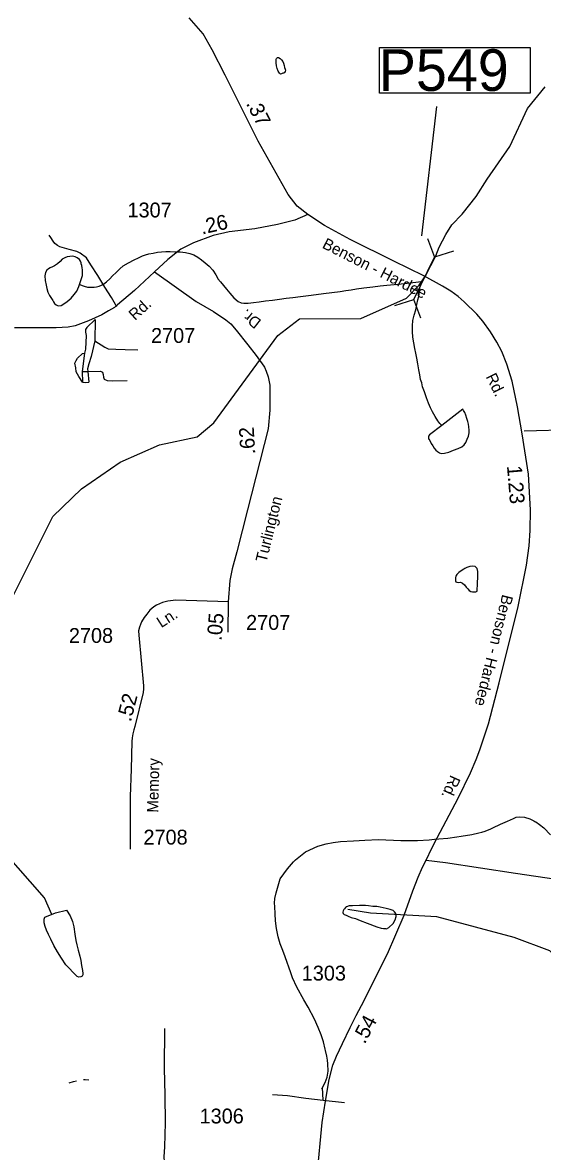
# Model space of a CAD drawing. Extents: x 2082433 to 2279600, y 546599 to 755198.
# Drawn here: x 2120566 to 2124939, y 611701 to 621201 of the extents above; entities that cross this region are included whole.
import ezdxf

# ---------------------------------------------------------------- set-up
doc = ezdxf.new("R2010")
doc.units = 0
for name, color, linetype in [('Exist Hydrographic Creek Single Shore', 7, 'Continuous'), ('Exist Hydrographic Misc Water Feature', 7, 'Continuous'), ('Exist Hydrographic Pond Under 1500 Sq Ft', 7, 'Continuous'), ('Exist Road Non-System Type 51', 7, 'Continuous'), ('Exist Road Secondary Mileage Hundredths English Label', 7, 'Continuous'), ('Exist Road Secondary Structure Pipe CELL', 7, 'Continuous'), ('Exist Road Secondary Structure Pipe Number Label', 7, 'Continuous'), ('Exist Road Secondary Type 51 Attributed', 7, 'Continuous'), ('Exist Road Secondary Type 51 Label', 7, 'Continuous'), ('Exist Road Secondary Type 51 Number Label', 7, 'Continuous')]:
    doc.layers.add(name, color=color, linetype=linetype)

msp = doc.modelspace()

# ---------------------------------------------------------------- linework, layer by layer
at = {"layer": 'Exist Hydrographic Creek Single Shore'}
for points in [[(2120366.5, 616142.3), (2120820.5, 617045), (2121061.5, 617276.4), (2121385.5, 617502.8), (2121717.6, 617646.9), (2122034.7, 617715.9), (2122175.5, 617831.2), (2122713.6, 618568.2), (2122896.5, 618708.9), (2123412.6, 618711.5), (2123795.7, 618881), (2123902.7, 618990.3), (2123955.2, 619069), (2124043.7, 619239), (2124069.9, 619311.8), (2124125.2, 619416.5), (2124177.5, 619497.9), (2124262.7, 619587.4), (2124380.8, 619738.6), (2124474.6, 619884.1), (2124664.7, 620159.2), (2124812.8, 620477.6), (2124962.7, 620661.6)], [(2121044.4, 618997.2), (2121085.2, 618981.3), (2121113.1, 618975.5), (2121139.1, 618973.6), (2121167.2, 618973.8), (2121188.8, 618975.8), (2121211.1, 618981.8), (2121230.6, 618989.8), (2121246.8, 618999.8), (2121271, 619020.1), (2121298.5, 619044.3), (2121322.4, 619068.3), (2121352, 619098.3), (2121384.2, 619128.3), (2121412.1, 619154.5), (2121458.2, 619178.8), (2121503.7, 619203.1), (2121540, 619221.2), (2121575.9, 619237.2), (2121599.7, 619247.4), (2121627.8, 619255.7), (2121663.7, 619261.6), (2121699.5, 619268), (2121735.4, 619271.9), (2121771.5, 619274.1), (2121807.2, 619274.4), (2121847.4, 619272.8), (2121891.7, 619270.5), (2121935.8, 619267.1), (2121973.5, 619258.9), (2122007.7, 619245.2), (2122041.4, 619225.6), (2122071.7, 619205.6), (2122101.8, 619179.5), (2122135.5, 619149.7), (2122165.8, 619117.9), (2122192.5, 619078.2), (2122202.3, 619058)], [(2122202.3, 619058), (2122208.5, 619044.1), (2122230.4, 619018.1), (2122256.5, 618988.6), (2122280.9, 618958.6), (2122308.7, 618924.7), (2122343, 618884.7), (2122378.9, 618854.9), (2122405.3, 618843.2), (2122427.1, 618839.1), (2122462.9, 618839.3), (2122508.9, 618845.3), (2122557.3, 618851.9), (2122608.7, 618859.8), (2122668.8, 618866.2), (2122726.8, 618872.4), (2122782.6, 618880.6), (2122840.7, 618886.8), (2122902.8, 618895.3), (2122972.5, 618903.4), (2123036.5, 618911.9), (2123098.2, 618920), (2123168.5, 618928.5), (2123236.6, 618938.8), (2123286.4, 618945.1), (2123330.3, 618951), (2123374.2, 618959.4), (2123438, 618969.6), (2123512, 618977.9), (2123574.3, 618984.3), (2123629.7, 618990.5), (2123692, 618996.9), (2123751.7, 619002.8), (2123799.9, 619008.9), (2123922.7, 619023)], [(2124092.9, 617808.8), (2124076.9, 617826.6), (2124059.1, 617850.4), (2124036.7, 617884.6), (2124015, 617924.4), (2123996.3, 617958.4), (2123980.5, 617998.1), (2123963.9, 618042), (2123945.9, 618094.2), (2123931.5, 618136.1), (2123923.5, 618169.8), (2123913.3, 618197.7), (2123907.3, 618235.9), (2123898.9, 618279.8), (2123890.7, 618329.7), (2123882.7, 618375.5), (2123872.7, 618417.6), (2123864.3, 618459.4), (2123856.3, 618505.6), (2123849.9, 618553.7), (2123845.8, 618601.3), (2123845.6, 618647.6), (2123849.3, 618693.2), (2123859.4, 618737.5), (2123872.9, 618783.4), (2123882.7, 618829.7), (2123890.7, 618867.4), (2123898.3, 618895.5), (2123912.4, 619006)], [(2120812.4, 613695.8), (2120751.4, 613834.8), (2120408.5, 614225.5), (2120090.5, 614474.7), (2120048.5, 614606.8)], [(2126508.5, 610011.1), (2126398.6, 610387.3), (2126277.6, 611226.3), (2126201.5, 611519.9), (2126100.6, 611767.9), (2126040.6, 612051.2), (2125923.5, 612224.2), (2125547.6, 612550.1), (2125261.6, 613139.8), (2125002.6, 613387.8), (2124701.6, 613502.1), (2124051.5, 613676.1), (2123493.6, 613707.1), (2123301.5, 613737.2)]]:
    msp.add_lwpolyline(points, dxfattribs=at)
at = {"layer": 'Exist Hydrographic Misc Water Feature'}
for p, q in [((2124220.2, 614348.8), (2124254.7, 614354.1)), ((2122967.4, 612916.1), (2122933.1, 612977.3))]:
    msp.add_line(p, q, dxfattribs=at)
for points in [[(2122770.3, 620823.9), (2122774.4, 620808.3), (2122776.5, 620800.2), (2122774.4, 620790), (2122770.5, 620782.1), (2122762.7, 620776), (2122756.4, 620774.1), (2122744.7, 620770.2), (2122734.6, 620768), (2122726.6, 620774.1), (2122716.4, 620791.9), (2122706.3, 620815.7), (2122702.4, 620837.8), (2122698.3, 620861.9), (2122697.9, 620879.8), (2122700, 620891.7), (2122702, 620899.9), (2122710, 620906), (2122720.1, 620905.7), (2122732, 620897.8), (2122743.9, 620887.9), (2122754.3, 620874.1), (2122760.3, 620858.2), (2122766, 620839.9), (2122770.3, 620823.9)], [(2124521.9, 614424), (2124586.5, 614455.3), (2124644.5, 614481.2)], [(2124521.9, 614424), (2124586.5, 614455.3), (2124644.5, 614481.2)], [(2124644.5, 614481.2), (2124695.3, 614504), (2124719.3, 614512.5), (2124744.4, 614516.8), (2124788.4, 614513.4), (2124833.8, 614499.7), (2124867.2, 614482.9)], [(2124644.5, 614481.2), (2124695.3, 614504), (2124719.3, 614512.5), (2124744.4, 614516.8), (2124788.4, 614513.4), (2124833.8, 614499.7), (2124867.2, 614482.9)], [(2124867.2, 614482.9), (2124876.4, 614478.3), (2124883, 614473.9)], [(2124867.2, 614482.9), (2124876.4, 614478.3), (2124883, 614473.9)], [(2124254.7, 614354.1), (2124344.7, 614368.1), (2124403.4, 614380.7), (2124429.8, 614388.3)], [(2124254.7, 614354.1), (2124344.7, 614368.1), (2124403.4, 614380.7), (2124429.8, 614388.3)], [(2124429.8, 614388.3), (2124458.5, 614396.8), (2124490.5, 614409.7)], [(2124429.8, 614388.3), (2124458.5, 614396.8), (2124490.5, 614409.7)], [(2124490.5, 614409.7), (2124500.5, 614413.8), (2124521.9, 614424)], [(2124490.5, 614409.7), (2124500.5, 614413.8), (2124521.9, 614424)], [(2124883, 614473.9), (2124914.5, 614452.8), (2124950.6, 614422.8), (2125007.4, 614363.8)], [(2124883, 614473.9), (2124914.5, 614452.8), (2124950.6, 614422.8), (2125007.4, 614363.8)], [(2123050.4, 614270.7), (2123118.5, 614290.1), (2123178.4, 614301.8), (2123239.3, 614308.2), (2123349.8, 614315.1)], [(2123050.4, 614270.7), (2123118.5, 614290.1), (2123178.4, 614301.8), (2123239.3, 614308.2), (2123349.8, 614315.1)], [(2123349.8, 614315.1), (2123446.4, 614321.1), (2123560.4, 614324.9), (2123749.2, 614318.2)], [(2123349.8, 614315.1), (2123446.4, 614321.1), (2123560.4, 614324.9), (2123749.2, 614318.2)], [(2123749.2, 614318.2), (2123788.2, 614316.8), (2123795.6, 614317)], [(2123795.6, 614317), (2123888.5, 614318.8), (2123987.5, 614324), (2124030.6, 614327.4)], [(2123795.6, 614317), (2123888.5, 614318.8), (2123987.5, 614324), (2124030.6, 614327.4)], [(2124030.6, 614327.4), (2124068.5, 614330.4), (2124142.5, 614338.2), (2124220.2, 614348.8)], [(2124030.6, 614327.4), (2124068.5, 614330.4), (2124142.5, 614338.2), (2124220.2, 614348.8)], [(2122845.8, 614136.9), (2122862.4, 614155.7), (2122945.6, 614221.7), (2123050.4, 614270.7)], [(2122845.8, 614136.9), (2122862.4, 614155.7), (2122945.6, 614221.7), (2123050.4, 614270.7)], [(2122687.7, 613760.7), (2122686.5, 613790.9), (2122689.1, 613828.1), (2122700.4, 613877.1), (2122732.2, 613994.8), (2122793.3, 614078), (2122845.8, 614136.9)], [(2122687.7, 613760.7), (2122686.5, 613790.9), (2122689.1, 613828.1), (2122700.4, 613877.1), (2122732.2, 613994.8), (2122793.3, 614078), (2122845.8, 614136.9)], [(2122754.5, 613392), (2122733.6, 613449.1), (2122716.4, 613508), (2122702.4, 613576.7), (2122694.5, 613641.1), (2122690.6, 613701), (2122687.7, 613760.7)], [(2122754.5, 613392), (2122733.6, 613449.1), (2122716.4, 613508), (2122702.4, 613576.7), (2122694.5, 613641.1), (2122690.6, 613701), (2122687.7, 613760.7)], [(2123699.4, 613650.2), (2123709.3, 613678.3), (2123705.2, 613702.2), (2123695.1, 613718.2), (2123683, 613728.2), (2123657, 613736.1), (2123625, 613743.9), (2123598.9, 613751.8), (2123572.9, 613757.7), (2123545, 613761.5), (2123511, 613763.4), (2123474.9, 613767.2), (2123450.9, 613769.1), (2123399, 613770.9), (2123341, 613768.7), (2123312.9, 613766.6), (2123290.9, 613760.4), (2123286.8, 613758.4), (2123282.9, 613754.4), (2123273.1, 613742.4), (2123269.2, 613736.4), (2123265.1, 613730.4), (2123263.3, 613724.3), (2123261.2, 613714.3), (2123261.2, 613710.3), (2123263.3, 613702.4), (2123271.3, 613694.4), (2123287.5, 613688.5), (2123303.5, 613680.5), (2123331.3, 613670.6), (2123367.4, 613660.8), (2123405.4, 613645), (2123465.4, 613621.2), (2123545.6, 613591.6), (2123583.8, 613579.8), (2123601.6, 613575.9), (2123617.6, 613575.9), (2123627.6, 613574), (2123645.7, 613586.1), (2123683.4, 613618.2), (2123699.4, 613650.2)], [(2122933.1, 612977.3), (2122873.5, 613084.5), (2122836.3, 613162.8), (2122821.4, 613203.2), (2122774.2, 613338.7), (2122754.5, 613392)], [(2122933.1, 612977.3), (2122873.5, 613084.5), (2122836.3, 613162.8), (2122821.4, 613203.2), (2122774.2, 613338.7), (2122754.5, 613392)], [(2123052.5, 612743.1), (2123020.5, 612812.8), (2122967.4, 612916.1)], [(2123052.5, 612743.1), (2123020.5, 612812.8), (2122967.4, 612916.1)], [(2123096.4, 612624.1), (2123077.5, 612682.1), (2123052.5, 612743.1)], [(2123096.4, 612624.1), (2123077.5, 612682.1), (2123052.5, 612743.1)], [(2123115.2, 612549.4), (2123112.3, 612562.6), (2123096.4, 612624.1)], [(2123115.2, 612549.4), (2123112.3, 612562.6), (2123096.4, 612624.1)], [(2123130.2, 612468.4), (2123125.3, 612501.7), (2123115.2, 612549.4)], [(2123130.2, 612468.4), (2123125.3, 612501.7), (2123115.2, 612549.4)], [(2123082, 612226.8), (2123089.4, 612237.8), (2123112.6, 612282.2), (2123128.3, 612324.6), (2123136.3, 612377.5), (2123134.7, 612438.2), (2123130.2, 612468.4)], [(2123093.3, 612132.1), (2123089.4, 612237.8), (2123112.6, 612282.2), (2123128.3, 612324.6), (2123136.3, 612377.5), (2123134.7, 612438.2), (2123130.2, 612468.4)], [(2120957.2, 612277.7), (2120995.4, 612290.5), (2121018.1, 612296.1)], [(2121078, 612305.3), (2121093.2, 612306.7), (2121122.7, 612304.6)], [(2122667, 612181), (2122793.8, 612172.4), (2122949.3, 612149.3), (2123093.3, 612132.1)], [(2123093.3, 612132.1), (2123274.7, 612111.9)]]:
    msp.add_lwpolyline(points, dxfattribs=at)
at = {"layer": 'Exist Hydrographic Pond Under 1500 Sq Ft'}
for points in [[(2121044.4, 618997.2), (2121056.5, 619029.1), (2121068.6, 619073.1), (2121070.6, 619103.2), (2121070.2, 619119), (2121068.2, 619137.2), (2121064.3, 619157.3), (2121060, 619169.3), (2121057.7, 619179.3), (2121052, 619193.2), (2121044.2, 619207), (2121026.1, 619221), (2121007.7, 619230.7), (2120988, 619234.9), (2120963.8, 619232.5), (2120941.5, 619228.6), (2120920.1, 619222.5), (2120899.8, 619208.5), (2120882, 619190.5), (2120858.2, 619170.2), (2120834.2, 619153.9), (2120816.4, 619146.1), (2120797.9, 619138), (2120784.4, 619129.9), (2120770.4, 619117.8), (2120758.6, 619097.7), (2120752.2, 619069.8), (2120754.5, 619029.7), (2120764.9, 618990.1), (2120770.9, 618962), (2120777.2, 618931.8), (2120791.4, 618904.1), (2120809.6, 618878.3), (2120819.7, 618862.2), (2120825.2, 618850.3), (2120833.4, 618838.1), (2120847.5, 618826.3), (2120866, 618816.2), (2120889.8, 618818.7), (2120913.2, 618834.6), (2120941.7, 618854.6), (2120973.4, 618882.7), (2121001.1, 618913), (2121021, 618941.2), (2121038.9, 618979), (2121044.4, 618997.2)], [(2124092.9, 617808.8), (2123989.4, 617730.3), (2123981.8, 617720.1), (2123979.3, 617708.3), (2123982, 617698.2), (2123983.8, 617694.3), (2123992, 617682.5), (2124003.7, 617658.4), (2124016, 617638.3), (2124027.7, 617618.7), (2124042.1, 617602.7), (2124055.8, 617590.5), (2124074.2, 617578.8), (2124088, 617574.7), (2124114.2, 617576.8), (2124152.2, 617586.9), (2124191.9, 617601.1), (2124229.9, 617615.3), (2124259.8, 617629.4), (2124281.6, 617647.6), (2124295.7, 617667.8), (2124305.5, 617693.9), (2124317.4, 617719.7), (2124323, 617748), (2124323.2, 617769.8), (2124321.1, 617797.7), (2124317, 617821.9), (2124310.9, 617843.9), (2124304.5, 617869.6), (2124294.9, 617897.4), (2124286.5, 617919.4), (2124276.4, 617935.5), (2124270.3, 617947.4), (2124092.9, 617808.8)], [(2124286.1, 616605.9), (2124278.3, 616602.2), (2124256.3, 616588), (2124234.6, 616571.9), (2124218.2, 616555.7), (2124210.6, 616543.4), (2124206.5, 616531.5), (2124206.9, 616515.6), (2124206.7, 616501.5), (2124210.8, 616493.5), (2124218.6, 616491.5), (2124232.8, 616489.8), (2124249, 616491.9), (2124266.6, 616483.9), (2124284.8, 616468.2), (2124298.8, 616450.2), (2124311.1, 616434.2), (2124323.2, 616420.2), (2124337.1, 616414.4), (2124351.3, 616410.2), (2124365.4, 616410.6), (2124379.4, 616410.5), (2124388.8, 616416.3), (2124392.5, 616484.3), (2124394.3, 616536.4), (2124394.5, 616580.5), (2124390.4, 616606.3), (2124382.2, 616616.4), (2124372.2, 616622.4), (2124352.5, 616626.2), (2124328.3, 616622.2), (2124302.3, 616613.9), (2124286.1, 616605.9)], [(2120843.9, 613707.9), (2120935.9, 613732.1), (2120965.9, 613684.2), (2120986.4, 613636.5), (2120996.4, 613590.3), (2121006.5, 613530.4), (2121012.8, 613476.3), (2121021.2, 613440.6), (2121033.1, 613394.5), (2121047.3, 613344.6), (2121055.5, 613306.8), (2121061.6, 613265), (2121070, 613222.7), (2121074.1, 613196.9), (2121074.1, 613186.8)], [(2121074.1, 613186.8), (2121068.4, 613174.7), (2121055.9, 613168.9), (2121040.3, 613166.8), (2121024.3, 613172.8), (2121008.1, 613188.7), (2120988, 613210.4), (2120959.9, 613240.6), (2120930, 613272.3), (2120893.9, 613326), (2120859.2, 613381.9), (2120829.3, 613433.6), (2120802.6, 613485.8), (2120784.6, 613525.5), (2120768.4, 613563.6), (2120756.5, 613593.4), (2120748.3, 613623.4), (2120748.1, 613655.5), (2120754, 613673.3), (2120843.9, 613707.9)]]:
    msp.add_lwpolyline(points, dxfattribs=at)
at = {"layer": 'Exist Road Non-System Type 51'}
for p, q in [((2121175.3, 618702), (2121173, 618522.6)), ((2121067.2, 618263.4), (2121115.5, 618265.7)), ((2121067.2, 618263.4), (2121070.7, 618175.5)), ((2121115.5, 618265.7), (2121123.6, 618175.5))]:
    msp.add_line(p, q, dxfattribs=at)
for points in [[(2121358.2, 618808.5), (2121312.8, 618887.3), (2121258, 618975.2), (2121198.4, 619073.3), (2121141, 619161.2), (2121103.6, 619222.4), (2121049.7, 619261.4), (2121021.3, 619274.3), (2120957.6, 619289.9), (2120879.7, 619312.8), (2120860.1, 619323.9), (2120837.9, 619341.3), (2120822.7, 619360.4), (2120804.5, 619391.1), (2120790.7, 619412.3)], [(2121175.3, 618702), (2121106.3, 618635.9), (2121096, 618617.5), (2121096, 618594.5), (2121099.4, 618568.1), (2121096, 618451.4), (2121087.9, 618419.8), (2121067.2, 618263.4)], [(2121173, 618522.6), (2121143.1, 618391.6), (2121123.6, 618327.8), (2121113.2, 618287.6), (2121115.5, 618265.7)], [(2121173, 618522.6), (2121256.9, 618468.6), (2121284.5, 618456), (2121350, 618451.4), (2121428.2, 618450.2), (2121535.1, 618445.6)], [(2121070.7, 618175.5), (2121038.5, 618223.8), (2121015.5, 618262.8), (2121013.2, 618296.2), (2121006.3, 618334.1), (2121015.5, 618356), (2121028.2, 618377.8), (2121070.7, 618415.2), (2121087.9, 618419.8)], [(2121115.5, 618265.7), (2121221.3, 618266.9), (2121238.5, 618258.8), (2121243.1, 618240.4), (2121245.4, 618216.3), (2121253.5, 618199), (2121276.5, 618188.7), (2121319, 618186.4), (2121444.3, 618188.7)], [(2121070.7, 618175.5), (2121093.7, 618170.9), (2121123.6, 618175.5)], [(2124786.1, 617763.9), (2125197.6, 617777.7)], [(2121760.4, 612735.8), (2121757, 612401.8), (2121763.9, 612175.3), (2121765, 611940.3), (2121759.7, 611740), (2121754.2, 611655.9), (2121759.3, 611575.8)]]:
    msp.add_lwpolyline(points, dxfattribs=at)
at = {"layer": 'Exist Road Secondary Structure Pipe CELL'}
for p, q in [((2123972.6, 619382.5), (2124030.9, 619226.5)), ((2123856.7, 618870.1), (2124030.9, 619226.5)), ((2124189.9, 619276.3), (2124030.9, 619226.5)), ((2123697.7, 618820.3), (2123856.7, 618870.1)), ((2123915, 618714.1), (2123856.7, 618870.1))]:
    msp.add_line(p, q, dxfattribs=at)
at = {"layer": 'Exist Road Secondary Structure Pipe Number Label'}
msp.add_line((2123924.6, 619407.2), (2124051.1, 620494.8), dxfattribs=at)
msp.add_lwpolyline([(2123569.7, 620990.2), (2124835.9, 620990.2), (2124835.9, 620606.3), (2123569.7, 620606.3)], close=True, dxfattribs=at)
at = {"layer": 'Exist Road Secondary Type 51 Attributed'}
msp.add_line((2122295.5, 616325.2), (2122292.7, 616070.5), dxfattribs=at)
for points in [[(2122965.8, 619584.8), (2122875.8, 619656.4), (2122800.9, 619754.8), (2122546.9, 620202.3), (2122269.5, 620757.2), (2122162.1, 620972), (2122083.8, 621106.3), (2121967.4, 621240.5)], [(2122965.8, 619584.8), (2122854.8, 619537.8), (2122709.3, 619500.8), (2122520, 619466.2), (2122303.2, 619440), (2122169.2, 619409.6), (2122004.9, 619347.4), (2121898.5, 619294.9), (2121787.9, 619206.6), (2121675.4, 619103.7)], [(2123961.5, 614151), (2124010, 614253.5), (2124052.5, 614340.6), (2124228.9, 614674.7), (2124334, 614887.1), (2124382.9, 614998), (2124413.2, 615079.4), (2124485.9, 615300.4), (2124573.8, 615643.1), (2124734.3, 616285.4), (2124806.3, 616634.6), (2124826.5, 616797.3), (2124837.3, 616926.2), (2124839.4, 617100.5), (2124822.9, 617400), (2124768.9, 617740.6), (2124729.3, 617966.7), (2124683.2, 618182.7), (2124639.3, 618327.4), (2124596.8, 618432.5), (2124554.3, 618511.7), (2124501.8, 618597.4), (2124437.7, 618688.1), (2124388, 618747.2), (2124280, 618851.6), (2124229.6, 618894.8), (2124167.7, 618940.1), (2124097.8, 618982.6), (2123941.6, 619068.3), (2123690.3, 619192.9), (2123320.3, 619374.6), (2123106.5, 619493.5), (2122965.8, 619584.8)], [(2121675.4, 619103.7), (2121506.5, 618946), (2121365.5, 618826.3), (2121339.8, 618803.9), (2121288.3, 618773.7), (2121232.4, 618740.2), (2121177.6, 618715.6), (2121121.7, 618692.1), (2121008.5, 618649.1), (2120950.5, 618638.6), (2120848.2, 618631.7), (2120498.2, 618631.7)], [(2121675.4, 619103.7), (2122026.7, 618854.3), (2122170.9, 618768.7), (2122276.2, 618700.5), (2122317.3, 618664.9), (2122361.5, 618612.4), (2122461, 618490.2), (2122532.1, 618399.3), (2122596, 618309.5), (2122602.1, 618299.7), (2122615.3, 618267.3), (2122632.6, 618219.3), (2122645, 618148.5), (2122645.5, 618105.1), (2122645.9, 617939), (2122631.7, 617782.7), (2122458.2, 617100.8), (2122367.2, 616745.7), (2122330.2, 616603.6), (2122310.3, 616504.2), (2122295.5, 616325.2)], [(2122295.5, 616325.2), (2121854.9, 616339.3), (2121788.9, 616330.8), (2121742.1, 616320.2), (2121693.1, 616296.8), (2121669.7, 616284), (2121636.9, 616255.5), (2121612.2, 616222.3), (2121588.8, 616194.7), (2121565.4, 616156.4), (2121550.5, 616113.9), (2121542, 616082), (2121542.8, 616044.8), (2121583.9, 615619.1), (2121584.2, 615593.5), (2121579.1, 615562.8), (2121509.5, 615278), (2121502.1, 615250.2), (2121494.2, 615215.2), (2121488.7, 615181.8), (2121485.5, 615151.2), (2121478.2, 614917.8), (2121472.3, 614687.7), (2121471.5, 614332.1), (2121470.8, 614315.4), (2121471.2, 614244)], [(2123044.5, 611501.7), (2123086.8, 611944.1), (2123113.5, 612124.9), (2123144.4, 612307), (2123174.7, 612425.8), (2123205.6, 612503.6), (2123257.5, 612608), (2123323, 612744.1), (2123372.7, 612843.4), (2123417.3, 612929.1), (2123635.5, 613364.7), (2123776.7, 613689), (2123850.1, 613894.9), (2123894.1, 614008), (2123930.8, 614092.2), (2123961.5, 614151)], [(2123961.5, 614151), (2124124.5, 614132.5), (2124712.8, 614041.8), (2125225.1, 613966.4)]]:
    msp.add_lwpolyline(points, dxfattribs=at)

# ---------------------------------------------------------------- texts
at = {"layer": 'Exist Road Secondary Mileage Hundredths English Label'}
for s, rotation, p in [('.37', 297.125, (2122443.1, 620520.5)), ('.26', 12.78621, (2122075.5, 619416.7)), ('.62', 93.42463, (2122523.8, 617569.9)), ('1.23', 274.68956, (2124640.4, 617469.7)), ('.05', 85.44788, (2122239.8, 615995.9)), ('.52', 75.51845, (2121476.5, 615310.7)), ('.54', 62.4312, (2123444.3, 612598.7))]:
    msp.add_text(s, height=125, rotation=rotation, dxfattribs=at).set_placement(p)
at = {"layer": 'Exist Road Secondary Structure Pipe Number Label'}
msp.add_text('P549', height=350, dxfattribs=at).set_placement((2123562.6, 620626.1))
at = {"layer": 'Exist Road Secondary Type 51 Label'}
for s, rotation, p in [('Benson - Hardee', 333.10484, (2123079.7, 619308)), ('Rd.', 42.05619, (2121510.9, 618689.6)), ('Dr.', 141.76685, (2122580.9, 618691.7)), ('Rd.', 296.20249, (2124460, 618221.3)), ('Turlington', 75.97352, (2122616.1, 616652.3)), ('Benson - Hardee', 255.91585, (2124602, 616393.4)), ('Ln.', 32.92399, (2121732.6, 616103.6)), ('Memory', 88.74649, (2121707, 614550.9)), ('Rd.', 245.88971, (2124167.2, 614874.6))]:
    msp.add_text(s, height=95, rotation=rotation, dxfattribs=at).set_placement(p)
at = {"layer": 'Exist Road Secondary Type 51 Number Label'}
for s, p in [('1307', (2121448.4, 619561.1)), ('2707', (2121646.3, 618505.1)), ('2707', (2122446.1, 616090.1)), ('2708', (2120955.3, 615980.4)), ('2708', (2121582.7, 614283.3)), ('1303', (2122914.3, 613138.9)), ('1306', (2122055, 611936.2))]:
    msp.add_text(s, height=125, dxfattribs=at).set_placement(p)

doc.saveas('drawing.dxf')
